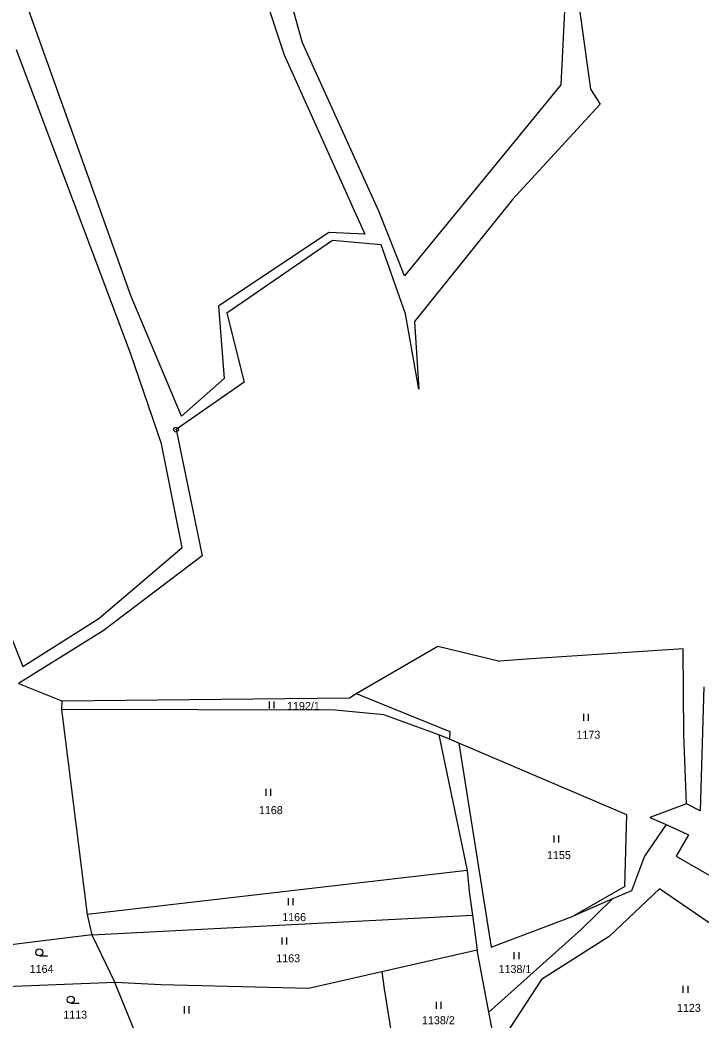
# Model space of a CAD drawing. Extents: x -744132 to -742433, y -984679 to -982287.
# Drawn here: x -742821.1 to -742676.3, y -983409.8 to -983197.5 of the extents above; entities that cross this region are included whole.
import ezdxf
from ezdxf.enums import TextEntityAlignment as Align

# ---------------------------------------------------------------- set-up
doc = ezdxf.new("R2010")
doc.units = 0
doc.header["$LTSCALE"] = 0.68
for name, color, linetype, lineweight in [('1', 7, 'Continuous', 25), ('3', 7, 'Continuous', 25), ('8', 7, 'Continuous', 25)]:
    doc.layers.add(name, color=color, linetype=linetype, lineweight=lineweight)
doc.layers.add('2', color=7, linetype='Continuous')

msp = doc.modelspace()

# ---------------------------------------------------------------- linework, layer by layer
at = {"layer": '1'}
for p, q in [((-742761.1, -983202.34), (-742770.02, -983170.68)), ((-742770.06, -983189.61), (-742764.98, -983204.88)), ((-742705.27, -983190.59), (-742706.27, -983211.27)), ((-742702.97, -983190.25), (-742699.94, -983212.21)), ((-742797.5, -983256.24), (-742820.73, -983191.17)), ((-742744.92, -983238.13), (-742761.1, -983202.34)), ((-742797.61, -983268.25), (-742821.79, -983203.81)), ((-742764.98, -983204.88), (-742747.87, -983242.97)), ((-742706.27, -983211.27), (-742739.44, -983251.86)), ((-742699.94, -983212.21), (-742697.92, -983215.36)), ((-742697.92, -983215.36), (-742716.56, -983235.6)), ((-742716.56, -983235.6), (-742737.33, -983261.52)), ((-742739.44, -983251.86), (-742744.92, -983238.13)), ((-742755.51, -983242.65), (-742778.96, -983258.25)), ((-742747.87, -983242.97), (-742755.51, -983242.65)), ((-742754.73, -983244.31), (-742777.17, -983259.73)), ((-742744.42, -983245.23), (-742754.73, -983244.31)), ((-742739.25, -983259.92), (-742744.42, -983245.23)), ((-742786.79, -983281.61), (-742797.5, -983256.24)), ((-742778.96, -983258.25), (-742777.73, -983273.62)), ((-742777.17, -983259.73), (-742773.48, -983274.43)), ((-742736.43, -983275.9), (-742739.25, -983259.92)), ((-742737.33, -983261.52), (-742736.43, -983275.9)), ((-742791.02, -983287.51), (-742797.61, -983268.25)), ((-742777.73, -983273.62), (-742786.79, -983281.61)), ((-742773.48, -983274.43), (-742787.96, -983284.49)), ((-742787.96, -983284.49), (-742782.42, -983311.28)), ((-742786.65, -983309.52), (-742791.02, -983287.51)), ((-742804.34, -983324.62), (-742786.65, -983309.52)), ((-742782.42, -983311.28), (-742803.4, -983327.24)), ((-742829.22, -983312.97), (-742820.49, -983334.77)), ((-742820.49, -983334.77), (-742804.34, -983324.62)), ((-742803.4, -983327.24), (-742821.43, -983338.41)), ((-742749.69, -983340.53), (-742732.38, -983330.46)), ((-742732.38, -983330.46), (-742719.24, -983333.62)), ((-742680.3, -983331.01), (-742713.55, -983333.25)), ((-742680.16, -983349.24), (-742680.3, -983331.01)), ((-742713.55, -983333.25), (-742719.24, -983333.62)), ((-742821.43, -983338.41), (-742812.22, -983342.05)), ((-742675.94, -983339.08), (-742676.68, -983365.44)), ((-742812.22, -983342.05), (-742751.12, -983341.43)), ((-742751.12, -983341.43), (-742749.69, -983340.53)), ((-742749.69, -983340.53), (-742729.86, -983348.57)), ((-742812.22, -983342.05), (-742812.25, -983343.88)), ((-742754.14, -983344.05), (-742812.25, -983343.88)), ((-742812.25, -983343.88), (-742806.82, -983387.45)), ((-742743.87, -983345.01), (-742754.14, -983344.05)), ((-742732.13, -983349.26), (-742743.87, -983345.01)), ((-742732.13, -983349.26), (-742726.15, -983378.07)), ((-742729.92, -983350.2), (-742732.13, -983349.26)), ((-742729.86, -983348.57), (-742729.92, -983350.2)), ((-742679.57, -983363.92), (-742680.16, -983349.24)), ((-742727.9, -983351.06), (-742729.92, -983350.2)), ((-742727.9, -983351.06), (-742721.02, -983394.36)), ((-742692.28, -983366.29), (-742727.9, -983351.06)), ((-742679.57, -983363.92), (-742687.34, -983366.83)), ((-742676.68, -983365.44), (-742679.57, -983363.92)), ((-742692.71, -983381.46), (-742692.28, -983366.29)), ((-742687.34, -983366.83), (-742683.9, -983368.33)), ((-742683.9, -983368.33), (-742688.51, -983375.04)), ((-742683.9, -983368.33), (-742679.13, -983370.5)), ((-742679.13, -983370.5), (-742681.79, -983375.07)), ((-742688.51, -983375.04), (-742691.27, -983382.41)), ((-742681.79, -983375.07), (-742659.97, -983387.64)), ((-742726.15, -983378.07), (-742806.82, -983387.45)), ((-742726.15, -983378.07), (-742725.72, -983382.57)), ((-742692.71, -983381.46), (-742703.67, -983387.82)), ((-742685.29, -983381.98), (-742696.01, -983392.12)), ((-742672.71, -983390.65), (-742685.29, -983381.98)), ((-742725.72, -983382.57), (-742725, -983387.58)), ((-742691.27, -983382.41), (-742695.33, -983384.14)), ((-742695.33, -983384.14), (-742703.67, -983387.82)), ((-742695.33, -983384.14), (-742701.92, -983390.63)), ((-742806.82, -983387.45), (-742806.36, -983389.66)), ((-742805.83, -983391.74), (-742725, -983387.58)), ((-742725, -983387.58), (-742724.05, -983395.02)), ((-742721.02, -983394.36), (-742703.67, -983387.82)), ((-742806.36, -983389.66), (-742805.83, -983391.74)), ((-742805.83, -983391.74), (-742833.43, -983395.18)), ((-742805.83, -983391.74), (-742800.93, -983401.85)), ((-742721.53, -983408.18), (-742701.92, -983390.63)), ((-742696.01, -983392.12), (-742710.35, -983401.23)), ((-742724.05, -983395.02), (-742744.27, -983399.62)), ((-742721.53, -983408.18), (-742724.05, -983395.02)), ((-742744.27, -983399.62), (-742759.85, -983403.16)), ((-742744.27, -983399.62), (-742743.74, -983403.23)), ((-742800.93, -983401.85), (-742830.73, -983403.05)), ((-742791.08, -983402.39), (-742800.93, -983401.85)), ((-742796.07, -983413.85), (-742800.93, -983401.85)), ((-742759.85, -983403.16), (-742791.08, -983402.39)), ((-742743.74, -983403.23), (-742741.99, -983414.27)), ((-742710.35, -983401.23), (-742720.04, -983415.98)), ((-742720.04, -983415.98), (-742721.53, -983408.18))]:
    msp.add_line(p, q, dxfattribs=at)
at = {"layer": '3'}
for p, q in [((-742768.131, -983343.68), (-742768.131, -983342.18)), ((-742767.13, -983343.68), (-742767.13, -983342.18)), ((-742701.361, -983346.33), (-742701.361, -983344.83)), ((-742700.36, -983346.33), (-742700.36, -983344.83)), ((-742768.851, -983362.26), (-742768.851, -983360.76)), ((-742767.85, -983362.26), (-742767.85, -983360.76)), ((-742707.661, -983372.15), (-742707.661, -983370.65)), ((-742706.66, -983372.15), (-742706.66, -983370.65)), ((-742764.091, -983385.48), (-742764.091, -983383.98)), ((-742763.09, -983385.48), (-742763.09, -983383.98)), ((-742765.401, -983393.8), (-742765.401, -983392.3)), ((-742764.4, -983393.8), (-742764.4, -983392.3)), ((-742816.973, -983396.22), (-742815.223, -983396.22)), ((-742716.141, -983396.9), (-742716.141, -983395.4)), ((-742715.14, -983396.9), (-742715.14, -983395.4)), ((-742680.261, -983404.07), (-742680.261, -983402.57)), ((-742679.26, -983404.07), (-742679.26, -983402.57)), ((-742810.303, -983406.28), (-742808.553, -983406.28)), ((-742786.181, -983408.42), (-742786.181, -983406.92)), ((-742785.18, -983408.42), (-742785.18, -983406.92)), ((-742732.691, -983407.47), (-742732.691, -983405.97)), ((-742731.69, -983407.47), (-742731.69, -983405.97))]:
    msp.add_line(p, q, dxfattribs=at)
for centre in [(-742816.9729, -983395.4698), (-742810.3029, -983405.5298)]:
    msp.add_circle(centre, 0.75, dxfattribs=at)
at = {"layer": '8'}
for radius in [0.5, 0.0303]:
    msp.add_circle((-742787.96, -983284.4899), radius, dxfattribs=at)

# ---------------------------------------------------------------- texts
at = {"layer": '2'}
for s, p in [('1192/1', (-742764.39, -983344.005)), ('1173', (-742702.94, -983350.115)), ('1168', (-742770.36, -983366.125)), ('1155', (-742709.2, -983375.665)), ('1166', (-742765.41, -983388.845)), ('1163', (-742766.68, -983397.585)), ('1164', (-742819.03, -983399.835)), ('1123', (-742681.61, -983408.105)), ('1113', (-742811.89, -983409.555))]:
    msp.add_text(s, height=1.7, dxfattribs=at).set_placement(p)
for s, p in [('1138/1', (-742716, -983399.865)), ('1138/2', (-742732.26, -983410.735))]:
    msp.add_text(s, height=1.7, dxfattribs=at).set_placement(p, align=Align.CENTER)

doc.saveas('drawing.dxf')
